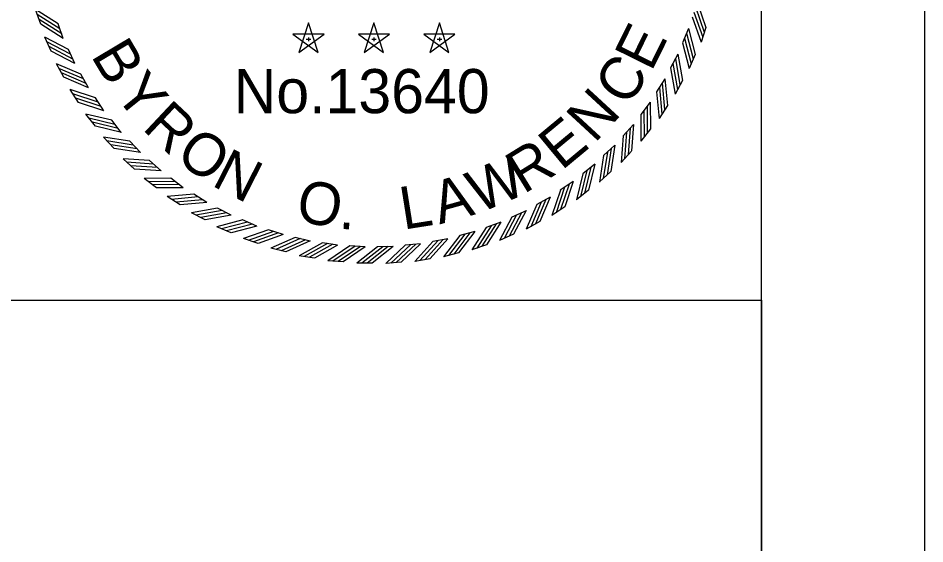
# Model space of a CAD drawing. Extents: x 0 to 1228740, y 0 to 152440.
# Drawn here: x 30.801 to 34, y 16.545 to 18.4 of the extents above; entities that cross this region are included whole.
import ezdxf

# ---------------------------------------------------------------- set-up
doc = ezdxf.new("R2010")
doc.units = 0
for name, color, linetype in [('R_Border', 7, 'Continuous'), ('R_No Plot', 7, 'Continuous'), ('STAMP', 7, 'Continuous')]:
    doc.layers.add(name, color=color, linetype=linetype)

msp = doc.modelspace()

# ---------------------------------------------------------------- linework, layer by layer
at = {"layer": 'R_Border'}
msp.add_line((33.4231, 0.5768), (33.4231, 21.4232), dxfattribs=at)
msp.add_lwpolyline([(33.9999, 22), (0, 22), (0, 0), (33.9999, 0)], close=True, dxfattribs=at)
at = {"layer": 'R_No Plot'}
for points in [[(33.4231, 17.4052), (33.4231, 10.8708), (1.516, 10.8708), (1.516, 21.4232), (25.1971, 21.4232), (25.1971, 20.4352), (28.7491, 20.4352), (28.7491, 20.0782), (29.1131, 20.0782), (29.1131, 20.1432), (30.6665, 20.1432)], [(30.6665, 20.1432), (30.6665, 17.4052), (33.4231, 17.4052)]]:
    msp.add_lwpolyline(points, dxfattribs=at)
at = {"layer": 'STAMP'}
for p, q in [((30.881, 18.3793), (30.8628, 18.4306)), ((30.9603, 18.3287), (30.9421, 18.3801)), ((31.8255, 18.3837), (31.7915, 18.2793)), ((31.8594, 18.2794), (31.8256, 18.3839)), ((32.0562, 18.3837), (32.0222, 18.2793)), ((32.0901, 18.2794), (32.0563, 18.3839)), ((32.287, 18.3837), (32.2529, 18.2793)), ((32.3209, 18.2794), (32.287, 18.3839)), ((33.1658, 18.363), (33.1444, 18.3129)), ((33.2276, 18.3674), (33.2104, 18.3158)), ((30.9178, 18.2836), (30.8955, 18.3332)), ((31.8804, 18.3439), (31.7706, 18.344)), ((31.7707, 18.3439), (31.8594, 18.2793)), ((31.7916, 18.2794), (31.8805, 18.3439)), ((31.8256, 18.3322), (31.8256, 18.3184)), ((32.1111, 18.3439), (32.0013, 18.344)), ((32.0014, 18.3439), (32.0902, 18.2793)), ((32.0223, 18.2794), (32.1112, 18.3439)), ((32.0563, 18.3322), (32.0563, 18.3184)), ((32.3418, 18.3439), (32.232, 18.344)), ((32.2321, 18.3439), (32.3209, 18.2793)), ((32.2531, 18.2794), (32.342, 18.3439)), ((32.2871, 18.3322), (32.2871, 18.3184)), ((31.8177, 18.3263), (31.834, 18.3263)), ((32.0484, 18.3263), (32.0647, 18.3263)), ((32.2791, 18.3263), (32.2955, 18.3263)), ((31.001, 18.2397), (30.9786, 18.2894)), ((33.1279, 18.2728), (33.1024, 18.2247)), ((33.1898, 18.272), (33.1685, 18.222)), ((30.9623, 18.1913), (30.936, 18.2389)), ((31.0489, 18.1544), (31.0225, 18.2021)), ((33.0827, 18.1861), (33.0533, 18.1402)), ((33.1443, 18.1802), (33.1189, 18.1321)), ((31.0144, 18.1029), (30.9842, 18.1482)), ((31.1037, 18.0733), (31.0735, 18.1187)), ((33.0305, 18.1033), (32.9974, 18.06)), ((33.0914, 18.0924), (33.0621, 18.0465)), ((31.0735, 18.0192), (31.0397, 18.0618)), ((31.165, 17.997), (31.1311, 18.0397)), ((32.9716, 18.0252), (32.935, 17.9847)), ((31.1394, 17.9406), (31.1022, 17.9803)), ((33.0314, 18.0092), (32.9984, 17.966)), ((31.2324, 17.9261), (31.1951, 17.9658)), ((32.9064, 17.9522), (32.8667, 17.9149)), ((32.9647, 17.9313), (32.9283, 17.891)), ((31.2115, 17.8678), (31.1712, 17.9042)), ((31.3054, 17.8609), (31.2649, 17.8975)), ((32.8355, 17.8848), (32.7928, 17.8509)), ((32.8919, 17.8592), (32.8522, 17.822)), ((31.2894, 17.8011), (31.2462, 17.8341)), ((31.3835, 17.802), (31.3402, 17.8351)), ((32.7592, 17.8235), (32.7138, 17.7933)), ((32.8133, 17.7933), (32.7707, 17.7595)), ((31.3725, 17.7411), (31.3267, 17.7704)), ((31.4663, 17.7498), (31.4204, 17.7792)), ((32.6781, 17.7687), (32.6304, 17.7423)), ((31.553, 17.7046), (31.5049, 17.7301)), ((32.7296, 17.7342), (32.6843, 17.704)), ((31.4604, 17.6882), (31.4123, 17.7136)), ((32.5928, 17.7208), (32.5431, 17.6984)), ((31.5522, 17.6427), (31.5022, 17.664)), ((31.6432, 17.6667), (31.5931, 17.6881)), ((32.5038, 17.6801), (32.4524, 17.6619)), ((32.6412, 17.6821), (32.5936, 17.6558)), ((31.7363, 17.6364), (31.6845, 17.6536)), ((31.8315, 17.6138), (31.7785, 17.6267)), ((32.4118, 17.6469), (32.3591, 17.633)), ((32.5489, 17.6376), (32.4993, 17.6153)), ((31.6476, 17.6049), (31.596, 17.6221)), ((31.9282, 17.5992), (31.8744, 17.6077)), ((32.0259, 17.5927), (31.9715, 17.5967)), ((32.1237, 17.5942), (32.0692, 17.5937)), ((32.2211, 17.6038), (32.1668, 17.5988)), ((32.3173, 17.6214), (32.2636, 17.6119)), ((32.4532, 17.6008), (32.4019, 17.5827)), ((31.7457, 17.5751), (31.6928, 17.588)), ((31.8459, 17.5536), (31.7922, 17.562)), ((32.3547, 17.572), (32.3021, 17.5582)), ((31.9476, 17.5404), (31.8934, 17.5444)), ((32.05, 17.5356), (31.9956, 17.5351)), ((32.1525, 17.5393), (32.0983, 17.5344)), ((32.2543, 17.5515), (32.2007, 17.5421))]:
    msp.add_line(p, q, dxfattribs=at)
for points in [[(30.9421, 18.38), (30.8628, 18.4307)], [(33.1904, 18.4396), (33.2219, 18.3509)], [(33.1961, 18.4562), (33.2276, 18.3675)], [(30.948, 18.3628), (30.8687, 18.4135)], [(30.9547, 18.3452), (30.8754, 18.3958)], [(33.179, 18.4044), (33.2104, 18.3157)], [(33.1849, 18.4215), (33.2163, 18.3328)], [(30.9604, 18.3286), (30.8811, 18.3793)], [(33.1658, 18.3631), (33.1898, 18.2721)], [(30.9786, 18.2893), (30.8954, 18.3333)], [(33.1588, 18.3471), (33.1828, 18.2561)], [(30.9859, 18.2727), (30.9027, 18.3167)], [(30.994, 18.2557), (30.9108, 18.2996)], [(33.1444, 18.313), (33.1685, 18.222)], [(33.1517, 18.3296), (33.1758, 18.2386)], [(31.0011, 18.2396), (30.9178, 18.2836)], [(33.1279, 18.2729), (33.1443, 18.1803)], [(31.0225, 18.202), (30.9359, 18.2389)], [(33.1111, 18.2406), (33.1275, 18.148)], [(33.1196, 18.2575), (33.136, 18.1649)], [(31.0311, 18.1861), (30.9446, 18.223)], [(31.0406, 18.1697), (30.9541, 18.2066)], [(33.1025, 18.2247), (33.1189, 18.132)], [(31.049, 18.1543), (30.9624, 18.1913)], [(33.0731, 18.1715), (33.0818, 18.0778)], [(33.0827, 18.1862), (33.0914, 18.0924)], [(31.0735, 18.1186), (30.9841, 18.1482)], [(33.0534, 18.1402), (33.0621, 18.0465)], [(33.0633, 18.1554), (33.072, 18.0617)], [(31.0834, 18.1034), (30.994, 18.1331)], [(31.0942, 18.0879), (31.0049, 18.1176)], [(31.1038, 18.0733), (31.0144, 18.1029)], [(33.0086, 18.0743), (33.0095, 17.9802)], [(33.0197, 18.0896), (33.0207, 17.9955)], [(33.0305, 18.1034), (33.0314, 18.0093)], [(31.1311, 18.0397), (31.0396, 18.0618)], [(31.1422, 18.0254), (31.0508, 18.0475)], [(32.9974, 18.06), (32.9984, 17.9659)], [(31.1543, 18.0108), (31.0628, 18.033)], [(31.1651, 17.997), (31.0736, 18.0192)], [(32.9597, 18.0124), (32.9529, 17.9185)], [(32.9716, 18.0253), (32.9648, 17.9314)], [(31.1951, 17.9658), (31.1021, 17.9803)], [(32.9351, 17.9848), (32.9283, 17.8909)], [(32.9474, 17.9981), (32.9405, 17.9042)], [(31.2074, 17.9524), (31.1144, 17.967)], [(31.2206, 17.9389), (31.1276, 17.9535)], [(32.9064, 17.9523), (32.8919, 17.8593)], [(31.2325, 17.9261), (31.1395, 17.9406)], [(32.8667, 17.9149), (32.8522, 17.8219)], [(32.8801, 17.9272), (32.8655, 17.8342)], [(32.8936, 17.9404), (32.879, 17.8474)], [(31.265, 17.8974), (31.1711, 17.9042)], [(31.2783, 17.8851), (31.1844, 17.892)], [(32.8355, 17.8849), (32.8133, 17.7934)], [(31.2926, 17.8728), (31.1987, 17.8796)], [(31.3055, 17.8609), (31.2116, 17.8677)], [(32.7928, 17.8509), (32.7707, 17.7595)], [(32.8071, 17.862), (32.785, 17.7706)], [(32.8217, 17.8741), (32.7995, 17.7827)], [(31.3402, 17.8351), (31.2461, 17.8341)], [(31.3545, 17.8239), (31.2604, 17.823)], [(32.7592, 17.8236), (32.7296, 17.7343)], [(31.3698, 17.8128), (31.2757, 17.8118)], [(31.3836, 17.802), (31.2895, 17.8011)], [(32.7139, 17.7933), (32.6843, 17.7039)], [(32.7291, 17.8032), (32.6994, 17.7138)], [(32.7446, 17.814), (32.7149, 17.7247)], [(31.4204, 17.7791), (31.3267, 17.7704)], [(31.4356, 17.7692), (31.3418, 17.7605)], [(31.4517, 17.7594), (31.358, 17.7507)], [(32.6628, 17.7604), (32.6259, 17.6739)], [(32.6782, 17.7688), (32.6412, 17.6822)], [(31.4663, 17.7498), (31.3726, 17.7411)], [(31.5049, 17.73), (31.4122, 17.7136)], [(32.6305, 17.7423), (32.5936, 17.6557)], [(32.6464, 17.7509), (32.6095, 17.6644)], [(31.5208, 17.7214), (31.4282, 17.705)], [(31.5377, 17.7129), (31.4451, 17.6965)], [(31.5531, 17.7046), (31.4604, 17.6882)], [(32.5432, 17.6984), (32.4992, 17.6152)], [(32.5598, 17.7057), (32.5158, 17.6225)], [(32.5768, 17.7138), (32.5329, 17.6306)], [(32.5929, 17.7209), (32.5489, 17.6376)], [(31.5932, 17.6881), (31.5022, 17.664)], [(31.6098, 17.6808), (31.5188, 17.6568)], [(31.6273, 17.6737), (31.5363, 17.6497)], [(31.6433, 17.6667), (31.5523, 17.6427)], [(32.4525, 17.6619), (32.4018, 17.5826)], [(32.4697, 17.6678), (32.419, 17.5885)], [(32.4873, 17.6745), (32.4367, 17.5952)], [(32.5039, 17.6802), (32.4532, 17.6009)], [(31.6846, 17.6535), (31.5959, 17.6221)], [(31.7017, 17.6476), (31.613, 17.6162)], [(31.7198, 17.6421), (31.6311, 17.6106)], [(31.7364, 17.6364), (31.6477, 17.6049)], [(31.7786, 17.6267), (31.6928, 17.588)], [(32.3591, 17.633), (32.3021, 17.5581)], [(32.3767, 17.6374), (32.3197, 17.5626)], [(32.3949, 17.6427), (32.3378, 17.5678)], [(32.4119, 17.647), (32.3548, 17.5721)], [(31.7961, 17.6222), (31.7103, 17.5835)], [(31.8146, 17.6182), (31.7288, 17.5795)], [(31.8316, 17.6139), (31.7458, 17.5752)], [(31.8744, 17.6077), (31.7921, 17.562)], [(31.8923, 17.6047), (31.81, 17.559)], [(31.911, 17.6021), (31.8287, 17.5565)], [(31.9283, 17.5993), (31.846, 17.5536)], [(31.9716, 17.5966), (31.8933, 17.5443)], [(31.9896, 17.5951), (31.9114, 17.5428)], [(32.0085, 17.5942), (31.9302, 17.5419)], [(32.1063, 17.5942), (32.0326, 17.5357)], [(32.1238, 17.5942), (32.0501, 17.5357)], [(32.1669, 17.5988), (32.0983, 17.5343)], [(32.1849, 17.6002), (32.1163, 17.5358)], [(32.2037, 17.6024), (32.1351, 17.538)], [(32.2211, 17.6038), (32.1526, 17.5394)], [(32.2637, 17.6119), (32.2007, 17.542)], [(32.2816, 17.6149), (32.2186, 17.545)], [(32.3001, 17.6186), (32.2371, 17.5487)], [(32.3174, 17.6215), (32.2544, 17.5516)], [(32.0259, 17.5927), (31.9477, 17.5404)], [(32.0693, 17.5936), (31.9956, 17.5351)], [(32.0874, 17.5936), (32.0137, 17.5351)]]:
    msp.add_lwpolyline(points, dxfattribs=at)

# ---------------------------------------------------------------- texts
for s, rotation, p in [('E', 63.7362, (33.0348, 18.208)), ('B', 300.7985, (31.0558, 18.2681)), ('C', 56.0754, (32.9504, 18.0834)), ('Y', 308.8241, (31.1366, 18.1326)), ('N', 47.3202, (32.8346, 17.9562)), ('R', 316.8497, (31.2355, 18.0098)), ('E', 39.6594, (32.7184, 17.8604)), ('O', 324.8753, (31.3505, 17.902)), ('R', 31.6338, (32.5841, 17.7777)), ('N', 332.9009, (31.4795, 17.8112)), ('W', 22.8786, (32.4261, 17.7098)), ('O', 349.3169, (31.7759, 17.6861)), ('A', 15.5826, (32.2877, 17.6721)), ('L', 9.0162, (32.16, 17.6535)), ('.', 357.3425, (31.9309, 17.6568))]:
    msp.add_text(s, height=0.1503, rotation=rotation, dxfattribs=at).set_placement(p)
msp.add_text('No.13640', height=0.15573, dxfattribs=at).set_placement((31.5614, 18.0647))

doc.saveas('drawing.dxf')
